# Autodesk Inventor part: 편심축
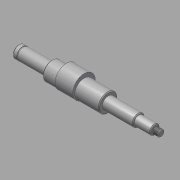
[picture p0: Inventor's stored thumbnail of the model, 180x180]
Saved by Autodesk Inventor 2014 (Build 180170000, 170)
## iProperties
Created: 2015-09
Part Number: 편심축
Material: 강철, 연강
Document SubType Name: Modeling
Designer: mduedu
Density: 1 g/cm^3
Appearance: 강철
Author: mduedu
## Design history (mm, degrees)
sketch "스케치1"
  geometry: L1 (-88.5, 0)-(88.5, 0); L2 (-88.5, 0)-(-88.5, 7.5); L3 (-88.5, 7.5)-(-47.35, 7.5); L4 (-47.35, 7.5)-(-47.35, 11.5); L5 (-47.35, 11.5)-(22.65, 11.5); L6 (22.65, 11.5)-(22.65, 7.5); L7 (22.65, 7.5)-(60.65, 7.5); L8 (60.65, 7.5)-(60.65, 6); L9 (60.65, 6)-(80.65, 6); L10 (80.65, 6)-(80.65, 3); L11 (80.65, 3)-(81.65, 3); L12 (81.65, 3)-(81.65, 4); L13 (81.65, 4)-(88.5, 4); L14 (88.5, 4)-(88.5, 0); 2 further points
  constraints: 28 end point, 10 parallel, 2 perpendicular, 1 coincident, 1 collinear, 1 horizontal, 1 midpoint
  dimensions: "d0" = 41.15 distance of L2.end L3.end; "d2" = 70 distance of L4.end L5.end; "d3" = 38 distance of L6.end L7.end; "d4" = 177 distance of L1.start L1.end; "d5" = 20 distance of L8.end L9.end; "d6" = 1 distance of L10.end L11.end; "d7" = 8 diameter of L13 L1; "d8" = 6 diameter of L11 L1; "d9" = 12 diameter of L9 L1; "d10" = 15 diameter of L7 L1; "d11" = 23 diameter of L5 L1; "d12" = 15 diameter of L3 L1
revolve "회전1" sketch "스케치1" stored, may be unused: angle "d13" = 90 deg
sketch "스케치2"
  geometry: L1 (-88.5, 7.5)-(-47.35, 7.5) reference; L2 (-88.5, -7.5)-(-88.5, 7.5) reference; L3 (88.5, -4)-(88.5, 4) reference; L4 (-88.5, 0)-(88.5, 0); L5 (-83.5, 7.5)-(-82.35, 7.5); L6 (-82.35, 7.5)-(-82.35, 7.15); L7 (-82.35, 7.15)-(-83.5, 7.15); L8 (-83.5, 7.15)-(-83.5, 7.5); 1 further point
  constraints: 10 end point, 2 midpoint, 2 parallel, 1 horizontal, 1 perpendicular, 1 point on line
  dimensions: "d14" = 5 distance between parallel lines of L8 L2; "d15" = 14.3 diameter of L7 L4; "d16" = 1.15 distance of L6.end L7.end
revolve "회전2" sketch "스케치2" stored, may be unused: angle "d17" = 90 deg
node "작업 평면1"
sketch "스케치3"
  geometry: C1 r 11.5 at (0, 0) reference; C2 r 14 at (0, 2.5); 1 further point
  constraints: 1 centre point, 1 tangent, 1 vertical alignment
  dimensions: "d19" = 28 diameter of C2
extrude "돌출1" join sketch "스케치3" distance "d21" = 22; taper "d22" = 0 deg
node "작업 평면2"
sketch "스케치4"
  geometry: L1 (10, 7.5)-(10, -7.5) reference; L2 (-10, 6)-(-10, -6) reference; L3 (10, 0)-(-10, 0); L4 (-5, -2)-(3, -2); L5 (3, 2)-(-5, 2); A1 r 2 centre (3, 0) between (3, -2) and (3, 2); A2 r 2 centre (-5, 0) between (-5, 2) and (-5, -2); 1 further point
  constraints: 6 end point, 4 point on circle, 4 tangent, 2 centre point, 2 midpoint, 2 parallel, 1 point on line
  dimensions: "d23" = 4 distance between parallel lines of L5 L4; "d25" = 12 dimension on A2 A1; "d26" = 3 distance edge to line of A2 L2
extrude "돌출2" cut sketch "스케치4" distance "d27" = 2.5; taper "d28" = 0 deg
chamfer "모따기1" distance "d29" = 1; stored, may be unused: second distance "d30" = 2, angle "d31" = 45 deg
feature "스레드1" dims "d32" = 10, "d33" = 0
chamfer "모따기2" distance "d34" = 1; stored, may be unused: second distance "d35" = 2, angle "d36" = 45 deg
chamfer "모따기3" distance "d37" = 1; stored, may be unused: second distance "d38" = 2, angle "d39" = 45 deg
node "솔리드1"
